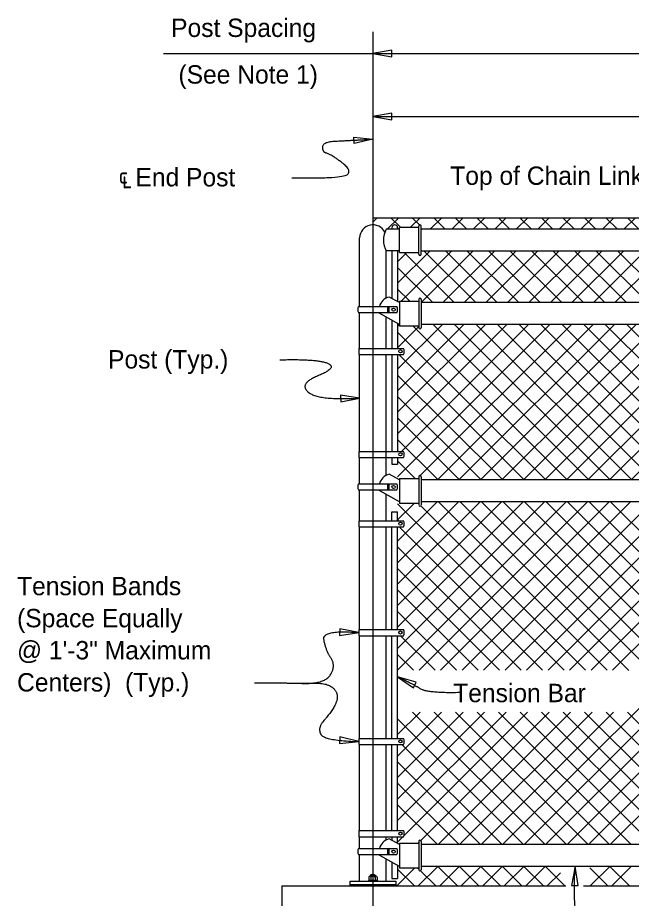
# Model space of a CAD drawing. Extents: x 110341.7 to 110413.5, y 110387.3 to 110417.8.
# Drawn here: x 110341.68 to 110348.41, y 110405.96 to 110415.62 of the extents above; entities that cross this region are included whole.
import ezdxf

# ---------------------------------------------------------------- set-up
doc = ezdxf.new("R2010")
doc.units = 0
for name, color, linetype in [('AdhocPoint_dp', 7, 'Continuous'), ('Border', 7, 'Continuous'), ('CL_Major', 7, 'Continuous'), ('Patterning', 7, 'Continuous'), ('PlotBorder_dp', 7, 'Continuous'), ('SheetBorder_dp', 7, 'Continuous')]:
    doc.layers.add(name, color=color, linetype=linetype)

msp = doc.modelspace()

# ---------------------------------------------------------------- linework, layer by layer
at = {"layer": 'AdhocPoint_dp'}
for p, q in [((110345.7862, 110413.3133), (110345.7862, 110413.2957)), ((110345.8487, 110413.3133), (110345.8487, 110413.2957)), ((110345.8673, 110413.0415), (110345.8673, 110413.3138)), ((110346.0803, 110413.3138), (110345.8673, 110413.3138)), ((110346.0803, 110413.022), (110346.0803, 110413.3316)), ((110346.1071, 110413.022), (110346.1071, 110413.3316)), ((110345.8674, 110413.2957), (110345.7237, 110413.2957)), ((110355.0484, 110413.2966), (110346.1071, 110413.2966)), ((110345.432, 110412.4493), (110345.432, 110413.2019)), ((110345.7237, 110412.5385), (110345.7237, 110413.058)), ((110345.8674, 110413.058), (110345.7237, 110413.058)), ((110345.7862, 110413.058), (110345.7862, 110412.5385)), ((110345.8487, 110413.058), (110345.8487, 110412.5023)), ((110345.8673, 110413.0415), (110346.0803, 110413.0415)), ((110355.0484, 110413.057), (110346.1071, 110413.057)), ((110345.8673, 110412.4919), (110345.7565, 110412.5532)), ((110345.4206, 110412.4493), (110345.8402, 110412.4493)), ((110345.7578, 110412.4415), (110345.7343, 110412.4415)), ((110345.8673, 110412.5066), (110345.8673, 110412.2344)), ((110345.8673, 110412.5066), (110346.0803, 110412.5066)), ((110346.0803, 110412.5261), (110346.0803, 110412.2165)), ((110346.1071, 110412.5261), (110346.1071, 110412.2165)), ((110355.0484, 110412.4912), (110346.1071, 110412.4912)), ((110345.4205, 110412.3815), (110345.8402, 110412.3815)), ((110345.432, 110411.9892), (110345.432, 110412.3815)), ((110345.8673, 110412.2525), (110345.6534, 110412.371)), ((110345.7578, 110412.4319), (110345.7343, 110412.4319)), ((110345.7578, 110412.421), (110345.7343, 110412.421)), ((110345.7578, 110412.4093), (110345.7343, 110412.4093)), ((110345.7578, 110412.3975), (110345.7343, 110412.3975)), ((110345.7578, 110412.3877), (110345.7343, 110412.3877)), ((110345.7237, 110411.9891), (110345.7237, 110412.3321)), ((110345.7862, 110412.2975), (110345.7862, 110411.9892)), ((110345.8487, 110412.2629), (110345.8487, 110411.9892)), ((110355.0484, 110412.2516), (110346.1071, 110412.2516)), ((110346.0803, 110412.2344), (110345.8673, 110412.2344)), ((110345.422, 110411.9891), (110345.9131, 110411.9891)), ((110345.422, 110411.9891), (110345.422, 110411.9215)), ((110345.422, 110411.9215), (110345.9123, 110411.9215)), ((110345.432, 110410.8603), (110345.432, 110411.9216)), ((110345.7237, 110410.5969), (110345.7237, 110411.9215)), ((110345.7862, 110411.9216), (110345.7862, 110410.8603)), ((110345.8487, 110411.9216), (110345.8487, 110410.8603)), ((110345.422, 110410.8603), (110345.9131, 110410.8603)), ((110345.422, 110410.8603), (110345.422, 110410.7927)), ((110345.422, 110410.7927), (110345.9123, 110410.7927)), ((110345.432, 110410.5048), (110345.432, 110410.7927)), ((110345.7862, 110410.7927), (110345.7862, 110410.718)), ((110345.8487, 110410.7927), (110345.8487, 110410.718)), ((110345.7862, 110410.718), (110345.8487, 110410.718)), ((110345.8673, 110410.5473), (110345.7565, 110410.6087)), ((110345.4206, 110410.5047), (110345.8402, 110410.5047)), ((110345.8673, 110410.5621), (110345.8673, 110410.2898)), ((110345.8673, 110410.5621), (110346.0803, 110410.5621)), ((110346.0803, 110410.5816), (110346.0803, 110410.272)), ((110346.1071, 110410.5816), (110346.1071, 110410.272)), ((110355.0484, 110410.5466), (110346.1071, 110410.5466)), ((110345.4205, 110410.4369), (110345.8402, 110410.4369)), ((110345.432, 110410.1), (110345.432, 110410.4369)), ((110345.8673, 110410.308), (110345.6534, 110410.4265)), ((110345.7578, 110410.4969), (110345.7343, 110410.4969)), ((110345.7578, 110410.4873), (110345.7343, 110410.4873)), ((110345.7578, 110410.4765), (110345.7343, 110410.4765)), ((110345.7578, 110410.4647), (110345.7343, 110410.4647)), ((110345.7578, 110410.453), (110345.7343, 110410.453)), ((110345.7578, 110410.4432), (110345.7343, 110410.4432)), ((110345.7237, 110410.1), (110345.7237, 110410.3876)), ((110346.0803, 110410.2898), (110345.8673, 110410.2898)), ((110355.0484, 110410.307), (110346.1071, 110410.307)), ((110345.7862, 110410.1982), (110345.8487, 110410.1982)), ((110345.7862, 110410.1), (110345.7862, 110410.1982)), ((110345.8487, 110410.1), (110345.8487, 110410.1982)), ((110345.422, 110410.1), (110345.422, 110410.0324)), ((110345.422, 110410.1), (110345.9131, 110410.1)), ((110345.422, 110410.0324), (110345.9123, 110410.0324)), ((110345.432, 110408.9056), (110345.432, 110410.0324)), ((110345.7237, 110408.9056), (110345.7237, 110410.0324)), ((110345.7862, 110408.9056), (110345.7862, 110410.0324)), ((110345.8487, 110408.9056), (110345.8487, 110410.0324)), ((110345.422, 110408.9056), (110345.422, 110408.838)), ((110345.422, 110408.9056), (110345.9131, 110408.9056)), ((110345.422, 110408.838), (110345.9123, 110408.838)), ((110345.432, 110407.7111), (110345.432, 110408.838)), ((110345.7237, 110407.7111), (110345.7237, 110408.838)), ((110345.7862, 110407.7111), (110345.7862, 110408.838)), ((110345.8487, 110407.7111), (110345.8487, 110408.838)), ((110345.422, 110407.7111), (110345.422, 110407.6435)), ((110345.422, 110407.7111), (110345.9131, 110407.7111)), ((110345.422, 110407.6435), (110345.9123, 110407.6435)), ((110345.432, 110406.7008), (110345.432, 110407.6435)), ((110345.7237, 110406.7008), (110345.7237, 110407.6435)), ((110345.7862, 110406.7008), (110345.7862, 110407.6435)), ((110345.8487, 110406.7008), (110345.8487, 110407.6435)), ((110345.422, 110406.7008), (110345.422, 110406.6332)), ((110345.422, 110406.7008), (110345.9131, 110406.7008)), ((110345.422, 110406.6332), (110345.9123, 110406.6332)), ((110345.432, 110406.5047), (110345.432, 110406.6332)), ((110345.7237, 110406.5968), (110345.7237, 110406.6332)), ((110345.8673, 110406.5473), (110345.7565, 110406.6087)), ((110345.7862, 110406.6332), (110345.7862, 110406.5922)), ((110345.8487, 110406.5576), (110345.8487, 110406.6332)), ((110345.8673, 110406.5621), (110345.8673, 110406.2898)), ((110345.8673, 110406.5621), (110346.0803, 110406.5621)), ((110346.0803, 110406.5816), (110346.0803, 110406.2719)), ((110346.1071, 110406.5816), (110346.1071, 110406.2719)), ((110355.0484, 110406.5466), (110346.1071, 110406.5466)), ((110345.4206, 110406.5047), (110345.8402, 110406.5047)), ((110345.7578, 110406.4969), (110345.7343, 110406.4969)), ((110345.7578, 110406.4873), (110345.7343, 110406.4873)), ((110345.7578, 110406.4765), (110345.7343, 110406.4765)), ((110345.7578, 110406.4647), (110345.7343, 110406.4647)), ((110345.7578, 110406.4529), (110345.7343, 110406.4529)), ((110345.4205, 110406.4369), (110345.8402, 110406.4369)), ((110345.432, 110406.1455), (110345.432, 110406.4369)), ((110345.8673, 110406.3079), (110345.6534, 110406.4265)), ((110345.7237, 110406.1455), (110345.7237, 110406.3875)), ((110345.7578, 110406.4431), (110345.7343, 110406.4431)), ((110345.7862, 110406.3529), (110345.7862, 110406.1768)), ((110345.8487, 110406.3183), (110345.8487, 110406.1768)), ((110346.0803, 110406.2898), (110345.8673, 110406.2898)), ((110355.0484, 110406.307), (110346.1071, 110406.307)), ((110345.5324, 110406.1903), (110345.5324, 110406.1526)), ((110345.6119, 110406.199), (110345.5437, 110406.199)), ((110345.5617, 110406.2199), (110345.552, 110406.2102)), ((110345.552, 110406.2102), (110345.552, 110406.199)), ((110345.552, 110406.2102), (110345.6035, 110406.2102)), ((110345.5551, 110406.1905), (110345.5551, 110406.1526)), ((110345.5617, 110406.2199), (110345.5922, 110406.2199)), ((110345.5922, 110406.2199), (110345.6035, 110406.2102)), ((110345.6005, 110406.1905), (110345.6005, 110406.1526)), ((110345.6035, 110406.2102), (110345.6035, 110406.199)), ((110345.6232, 110406.1903), (110345.6232, 110406.1526)), ((110345.7862, 110406.1768), (110345.8487, 110406.1768)), ((110345.458, 110406.1039), (110345.6976, 110406.1039)), ((110345.5281, 110406.1526), (110345.5281, 110406.1455)), ((110345.5281, 110406.1526), (110345.6276, 110406.1526)), ((110345.6232, 110406.1526), (110345.5324, 110406.1526)), ((110345.6276, 110406.1526), (110345.6276, 110406.1455))]:
    msp.add_line(p, q, dxfattribs=at)
msp.add_lwpolyline([(110345.3278, 110406.1455), (110345.8278, 110406.1455), (110345.8278, 110406.1039), (110345.3278, 110406.1039)], close=True, dxfattribs=at)
for centre, radius, start, end in [((110345.5778, 110413.1987), 0.1459, 26.2486, 178.74846), ((110345.8174, 110413.3133), 0.0312, 0, 180), ((110346.0936, 110413.332), 0.0134, 0, 180), ((110345.9373, 110413.1768), 0.2445, 150.92084, 209.07916), ((110346.0936, 110413.0222), 0.0134, 180, 0), ((110346.0936, 110412.5261), 0.0134, 0, 180), ((110346.0936, 110412.2163), 0.0134, 180, 0), ((110346.0936, 110410.5815), 0.0134, 0, 180), ((110346.0936, 110410.2717), 0.0134, 180, 0), ((110346.0936, 110406.5815), 0.0134, 0, 180), ((110346.0936, 110406.2717), 0.0134, 180, 0), ((110345.5438, 110406.1871), 0.0118, 16.59863, 164.70054), ((110345.5778, 110406.1642), 0.0347, 49.20147, 130.79853), ((110345.6118, 110406.1872), 0.0118, 15.15064, 163.50417)]:
    msp.add_arc(centre, radius, start, end, dxfattribs=at)
for centre, major_axis, start_param, end_param in [((110345.791, 110412.4173), (-0.146, 0), 4.95193, 6.05206), ((110345.4896, 110412.4153), (-0.0776, 0), 5.807767, 6.754779), ((110345.771, 110412.4153), (0.0776, 0), 5.810211, 6.75616), ((110345.791, 110412.4173), (-0.146, 0), 0.258558, 0.335209), ((110345.8436, 110411.956), (0.0776, 0), 5.801046, 6.744962), ((110345.8436, 110410.8272), (0.0776, 0), 5.801046, 6.744962), ((110345.791, 110410.4727), (-0.146, 0), 4.95193, 6.05206), ((110345.4896, 110410.4708), (-0.0776, 0), 5.807767, 6.754779), ((110345.771, 110410.4707), (0.0776, 0), 5.810211, 6.75616), ((110345.791, 110410.4727), (-0.146, 0), 0.258558, 0.335209), ((110345.8436, 110410.0669), (0.0776, 0), 5.800848, 6.744767), ((110345.8436, 110408.8725), (0.0776, 0), 5.801046, 6.744962), ((110345.8436, 110407.6781), (0.0776, 0), 5.810211, 6.745158), ((110345.8436, 110406.6677), (0.0776, 0), 5.800848, 6.744767), ((110345.791, 110406.4727), (-0.146, 0), 4.95193, 6.05206), ((110345.4896, 110406.4708), (-0.0776, 0), 5.807767, 6.754779), ((110345.771, 110406.4707), (0.0776, 0), 5.810211, 6.75616), ((110345.791, 110406.4727), (-0.146, 0), 0.258558, 0.335209)]:
    msp.add_ellipse(centre, major_axis=major_axis, ratio=0.957868, start_param=start_param, end_param=end_param, dxfattribs=at)
for centre, major_axis in [((110345.8044, 110412.4148), (-0.0178, 0)), ((110345.8795, 110411.9564), (-0.0177, 0)), ((110345.8795, 110410.8276), (-0.0177, 0)), ((110345.8044, 110410.4703), (-0.0178, 0)), ((110345.8795, 110410.0673), (-0.0177, 0)), ((110345.8795, 110408.8729), (-0.0177, 0)), ((110345.8795, 110407.6785), (-0.0177, 0)), ((110345.8795, 110406.6681), (-0.0177, 0)), ((110345.8044, 110406.4703), (-0.0178, 0))]:
    msp.add_ellipse(centre, major_axis=major_axis, ratio=0.957868, dxfattribs=at)
at = {"layer": 'Border'}
for p, q in [((110343.2819, 110415.2246), (110354.5778, 110415.2246)), ((110345.5778, 110414.5336), (110355.5778, 110414.5336)), ((110345.5778, 110406.1533), (110345.5778, 110406.1526))]:
    msp.add_line(p, q, dxfattribs=at)
for points in [[(110345.5778, 110415.2246), (110345.786, 110415.1893), (110345.786, 110415.2599)], [(110345.5778, 110414.5336), (110345.786, 110414.4983), (110345.786, 110414.5689)], [(110345.5778, 110414.2843), (110345.3717, 110414.2377), (110345.3679, 110414.3082)], [(110345.432, 110411.4438), (110345.2231, 110411.4753), (110345.2244, 110411.4048)], [(110345.422, 110408.8718), (110345.2147, 110408.9124), (110345.2129, 110408.8418)], [(110345.8486, 110408.3863), (110346.0223, 110408.266), (110346.0522, 110408.3299)], [(110345.422, 110407.6773), (110345.2167, 110407.7272), (110345.2118, 110407.6568)], [(110347.7928, 110406.307), (110347.7551, 110406.0992), (110347.8256, 110406.0983)]]:
    msp.add_lwpolyline(points, close=True, dxfattribs=at)
for points in [[(110344.6883, 110413.8606), (110345.234, 110413.8508), (110345.3565, 110413.9397), (110345.1123, 110414.121), (110345.0274, 110414.1393), (110345.0274, 110414.2572), (110345.3055, 110414.2694), (110345.5778, 110414.2843)], [(110344.5591, 110411.8642), (110344.9628, 110411.8757), (110345.1958, 110411.7787), (110344.761, 110411.6009), (110344.9767, 110411.4185), (110345.432, 110411.4438)], [(110344.2805, 110408.3227), (110344.5557, 110408.3227), (110345.0469, 110408.3079), (110345.1744, 110408.5069), (110345.0622, 110408.6754), (110345.0194, 110408.9096), (110345.422, 110408.8718)], [(110346.5469, 110408.2144), (110346.1792, 110408.2052), (110346.0222, 110408.3033), (110345.8487, 110408.3863)], [(110344.5507, 110408.3221), (110344.7919, 110408.313), (110345.0849, 110408.3216), (110345.2105, 110408.1958), (110345.1389, 110408.0174), (110344.9638, 110407.824), (110345.0503, 110407.687), (110345.422, 110407.6773)], [(110348.3978, 110405.4486), (110348.0551, 110405.4333), (110347.7577, 110405.6365), (110347.7928, 110406.307)]]:
    msp.add_open_spline(points, degree=2, dxfattribs=at)
at = {"layer": 'CL_Major'}
msp.add_line((110345.5778, 110415.4617), (110345.5778, 110401.2111), dxfattribs=at)
at = {"layer": 'Patterning'}
for p, q in [((110345.5778, 110413.4227), (110356.9648, 110413.4227)), ((110345.5778, 110413.3753), (110345.6251, 110413.4227)), ((110345.7338, 110413.2957), (110345.8608, 110413.4227)), ((110345.7736, 110413.4227), (110345.8825, 110413.3138)), ((110345.9876, 110413.3138), (110346.0965, 110413.4227)), ((110346.0093, 110413.4227), (110346.0874, 110413.3446)), ((110346.2062, 110413.2966), (110346.3322, 110413.4227)), ((110346.245, 110413.4227), (110346.371, 110413.2966)), ((110346.4419, 110413.2966), (110346.5679, 110413.4227)), ((110346.4807, 110413.4227), (110346.6067, 110413.2966)), ((110346.6776, 110413.2966), (110346.8036, 110413.4227)), ((110346.7164, 110413.4227), (110346.8425, 110413.2966)), ((110346.9133, 110413.2966), (110347.0394, 110413.4227)), ((110346.9521, 110413.4227), (110347.0782, 110413.2966)), ((110347.149, 110413.2966), (110347.2751, 110413.4227)), ((110347.1878, 110413.4227), (110347.3139, 110413.2966)), ((110347.3847, 110413.2966), (110347.5108, 110413.4227)), ((110347.4235, 110413.4227), (110347.5496, 110413.2966)), ((110347.6204, 110413.2966), (110347.7465, 110413.4227)), ((110347.6592, 110413.4227), (110347.7853, 110413.2966)), ((110347.8561, 110413.2966), (110347.9822, 110413.4227)), ((110347.8949, 110413.4227), (110348.021, 110413.2966)), ((110348.0918, 110413.2966), (110348.2179, 110413.4227)), ((110348.1306, 110413.4227), (110348.2567, 110413.2966)), ((110348.3275, 110413.2966), (110348.4536, 110413.4227)), ((110348.3663, 110413.4227), (110348.4924, 110413.2966)), ((110345.8487, 110412.7034), (110346.2023, 110413.057)), ((110345.8487, 110412.9391), (110345.9511, 110413.0415)), ((110345.8876, 110412.5066), (110346.438, 110413.057)), ((110345.919, 110413.0415), (110346.4694, 110412.4912)), ((110346.1078, 110412.4912), (110346.6737, 110413.057)), ((110346.1392, 110413.057), (110346.7051, 110412.4912)), ((110346.3435, 110412.4912), (110346.9094, 110413.057)), ((110346.3749, 110413.057), (110346.9408, 110412.4912)), ((110346.5792, 110412.4912), (110347.1451, 110413.057)), ((110346.6106, 110413.057), (110347.1765, 110412.4912)), ((110346.815, 110412.4912), (110347.3808, 110413.057)), ((110346.8463, 110413.057), (110347.4122, 110412.4912)), ((110347.0507, 110412.4912), (110347.6165, 110413.057)), ((110347.082, 110413.057), (110347.6479, 110412.4912)), ((110347.2864, 110412.4912), (110347.8522, 110413.057)), ((110347.3177, 110413.057), (110347.8836, 110412.4912)), ((110347.5221, 110412.4912), (110348.0879, 110413.057)), ((110347.5534, 110413.057), (110348.1193, 110412.4912)), ((110347.7578, 110412.4912), (110348.3236, 110413.057)), ((110347.7891, 110413.057), (110348.355, 110412.4912)), ((110347.9935, 110412.4912), (110348.5593, 110413.057)), ((110348.0248, 110413.057), (110348.5907, 110412.4912)), ((110348.2292, 110412.4912), (110348.795, 110413.057)), ((110348.2605, 110413.057), (110348.8264, 110412.4912)), ((110345.8487, 110412.8762), (110346.2337, 110412.4912)), ((110345.8487, 110412.6405), (110345.9778, 110412.5113)), ((110345.8487, 110411.7606), (110346.3397, 110412.2516)), ((110345.8487, 110411.2892), (110346.8111, 110412.2516)), ((110345.8487, 110410.5821), (110347.5182, 110412.2516)), ((110345.8487, 110411.0535), (110347.0468, 110412.2516)), ((110345.8487, 110411.5249), (110346.5754, 110412.2516)), ((110345.8487, 110412.232), (110345.8674, 110412.2507)), ((110345.8912, 110410.8603), (110347.2825, 110412.2516)), ((110346.0969, 110410.5946), (110347.7539, 110412.2516)), ((110346.2376, 110412.2516), (110347.9425, 110410.5466)), ((110346.2846, 110410.5466), (110347.9896, 110412.2516)), ((110346.4733, 110412.2516), (110348.1782, 110410.5466)), ((110346.5203, 110410.5466), (110348.2253, 110412.2516)), ((110346.709, 110412.2516), (110348.4139, 110410.5466)), ((110346.756, 110410.5466), (110348.461, 110412.2516)), ((110346.9447, 110412.2516), (110348.6496, 110410.5466)), ((110346.9917, 110410.5466), (110348.6967, 110412.2516)), ((110347.1804, 110412.2516), (110348.8853, 110410.5466)), ((110347.2274, 110410.5466), (110348.9324, 110412.2516)), ((110347.4161, 110412.2516), (110349.121, 110410.5466)), ((110347.4631, 110410.5466), (110349.1681, 110412.2516)), ((110347.6518, 110412.2516), (110349.3567, 110410.5466)), ((110347.6988, 110410.5466), (110349.4038, 110412.2516)), ((110347.8875, 110412.2516), (110349.5925, 110410.5466)), ((110347.9345, 110410.5466), (110349.6395, 110412.2516)), ((110348.1232, 110412.2516), (110349.8282, 110410.5466)), ((110348.1702, 110410.5466), (110349.8752, 110412.2516)), ((110348.3589, 110412.2516), (110350.0639, 110410.5466)), ((110348.4059, 110410.5466), (110350.1109, 110412.2516)), ((110345.8487, 110411.9963), (110346.0803, 110412.228)), ((110345.8487, 110412.1691), (110347.4711, 110410.5466)), ((110346.0191, 110412.2344), (110347.7068, 110410.5466)), ((110345.8605, 110411.9216), (110347.2354, 110410.5466)), ((110345.8487, 110411.6977), (110346.9997, 110410.5466)), ((110345.8487, 110411.462), (110346.764, 110410.5466)), ((110345.8487, 110411.2263), (110346.5283, 110410.5466)), ((110345.8487, 110410.9906), (110346.2926, 110410.5466)), ((110345.8487, 110410.7549), (110346.0414, 110410.5621)), ((110345.8487, 110408.9322), (110347.2235, 110410.307)), ((110345.8487, 110409.4036), (110346.7521, 110410.307)), ((110345.8487, 110408.6965), (110347.4593, 110410.307)), ((110345.8487, 110409.1679), (110346.9878, 110410.307)), ((110345.8487, 110409.6393), (110346.5164, 110410.307)), ((110345.8487, 110408.4608), (110347.695, 110410.307)), ((110345.8487, 110409.875), (110346.2807, 110410.307)), ((110345.8487, 110410.1107), (110346.0279, 110410.2899)), ((110345.8487, 110410.2835), (110347.6726, 110408.4596)), ((110346.0832, 110408.4596), (110347.9307, 110410.307)), ((110346.1043, 110410.2635), (110347.9083, 110408.4596)), ((110346.2965, 110410.307), (110348.144, 110408.4596)), ((110346.3189, 110408.4596), (110348.1664, 110410.307)), ((110346.5322, 110410.307), (110348.3834, 110408.4558)), ((110346.5546, 110408.4596), (110348.4021, 110410.307)), ((110346.7679, 110410.307), (110350.5283, 110406.5466)), ((110346.7903, 110408.4596), (110348.6378, 110410.307)), ((110346.9986, 110406.5466), (110350.7591, 110410.307)), ((110347.0036, 110410.307), (110350.764, 110406.5466)), ((110347.026, 110408.4596), (110348.8735, 110410.307)), ((110347.2343, 110406.5466), (110350.9948, 110410.307)), ((110347.2393, 110410.307), (110350.9997, 110406.5466)), ((110347.2617, 110408.4596), (110349.1092, 110410.307)), ((110347.47, 110406.5466), (110351.2305, 110410.307)), ((110347.475, 110410.307), (110351.2355, 110406.5466)), ((110347.4974, 110408.4596), (110349.3449, 110410.307)), ((110347.7057, 110406.5466), (110351.4662, 110410.307)), ((110347.7107, 110410.307), (110351.4712, 110406.5466)), ((110347.7331, 110408.4596), (110349.5806, 110410.307)), ((110347.9415, 110406.5466), (110351.7019, 110410.307)), ((110347.9464, 110410.307), (110351.7069, 110406.5466)), ((110347.9688, 110408.4596), (110349.8163, 110410.307)), ((110348.1772, 110406.5466), (110351.9376, 110410.307)), ((110348.1821, 110410.307), (110351.9426, 110406.5466)), ((110348.2045, 110408.4596), (110350.052, 110410.307)), ((110345.8487, 110410.1121), (110345.8607, 110410.1)), ((110345.864, 110410.0324), (110347.4369, 110408.4596)), ((110345.8504, 110409.8103), (110347.2012, 110408.4596)), ((110345.8487, 110409.5764), (110346.9655, 110408.4596)), ((110345.8487, 110409.3407), (110346.7298, 110408.4596)), ((110345.8487, 110409.105), (110346.4941, 110408.4596)), ((110345.8799, 110408.838), (110346.2584, 110408.4596)), ((110345.8487, 110408.6336), (110346.0227, 110408.4596)), ((110345.8487, 110407.0465), (110346.8013, 110407.9992)), ((110345.8487, 110406.8108), (110347.037, 110407.9992)), ((110345.8487, 110407.518), (110346.3299, 110407.9992)), ((110345.8487, 110407.2823), (110346.5656, 110407.9992)), ((110345.8487, 110407.7537), (110346.0942, 110407.9992)), ((110345.917, 110406.6435), (110347.2728, 110407.9992)), ((110346.0116, 110407.9992), (110347.4642, 110406.5466)), ((110346.1016, 110406.5923), (110347.5085, 110407.9992)), ((110346.2473, 110407.9992), (110347.6999, 110406.5466)), ((110346.2915, 110406.5466), (110347.7442, 110407.9992)), ((110346.483, 110407.9992), (110347.9356, 110406.5466)), ((110346.5272, 110406.5466), (110347.9799, 110407.9992)), ((110346.7187, 110407.9992), (110348.1713, 110406.5466)), ((110346.7629, 110406.5466), (110348.2156, 110407.9992)), ((110346.9544, 110407.9992), (110348.407, 110406.5466)), ((110347.1901, 110407.9992), (110348.6427, 110406.5466)), ((110347.4258, 110407.9992), (110348.8784, 110406.5466)), ((110347.6615, 110407.9992), (110349.1141, 110406.5466)), ((110347.8972, 110407.9992), (110349.3498, 110406.5466)), ((110348.1329, 110407.9992), (110349.5855, 110406.5466)), ((110348.3686, 110407.9992), (110349.8212, 110406.5466)), ((110345.8487, 110407.9265), (110347.2285, 110406.5466)), ((110345.8959, 110407.6435), (110346.9928, 110406.5466)), ((110345.8487, 110407.4551), (110346.7571, 110406.5466)), ((110345.8487, 110407.2193), (110346.5214, 110406.5466)), ((110345.8487, 110406.9836), (110346.2857, 110406.5466)), ((110345.8487, 110406.5751), (110345.9067, 110406.6332)), ((110346.0713, 110406.5621), (110346.0803, 110406.5711)), ((110345.8384, 110406.0935), (110346.0347, 110406.2898)), ((110345.8487, 110406.2765), (110346.0317, 110406.0935)), ((110346.0711, 110406.2898), (110346.0803, 110406.2806)), ((110346.0741, 110406.0935), (110346.2877, 110406.307)), ((110346.1007, 110406.2603), (110346.2674, 110406.0935)), ((110346.2896, 110406.307), (110346.5031, 110406.0935)), ((110346.3098, 110406.0935), (110346.5234, 110406.307)), ((110346.5253, 110406.307), (110346.7388, 110406.0935)), ((110346.5455, 110406.0935), (110346.7591, 110406.307)), ((110346.761, 110406.307), (110346.9745, 110406.0935)), ((110346.7812, 110406.0935), (110346.9948, 110406.307)), ((110346.9967, 110406.307), (110347.2103, 110406.0935)), ((110347.0169, 110406.0935), (110347.2305, 110406.307)), ((110347.2324, 110406.307), (110347.446, 110406.0935)), ((110347.2526, 110406.0935), (110347.4662, 110406.307)), ((110347.4681, 110406.307), (110347.6817, 110406.0935)), ((110347.9557, 110406.2908), (110348.1531, 110406.0935)), ((110347.9597, 110406.0935), (110348.1733, 110406.307)), ((110348.1752, 110406.307), (110348.3888, 110406.0935)), ((110348.1954, 110406.0935), (110348.409, 110406.307)), ((110345.5666, 110406.215), (110345.5874, 110406.215)), ((110345.5666, 110406.2053), (110345.5874, 110406.2053)), ((110347.4883, 110406.0935), (110347.6328, 110406.238)), ((110345.3278, 110406.1004), (110345.8278, 110406.1004)), ((110345.3278, 110406.0969), (110345.8278, 110406.0969))]:
    msp.add_line(p, q, dxfattribs=at)
msp.add_lwpolyline([(110345.3278, 110406.1039), (110345.8278, 110406.1039), (110345.8278, 110406.0935), (110345.3278, 110406.0935)], close=True, dxfattribs=at)
at = {"layer": 'PlotBorder_dp'}
for p, q in [((110344.5778, 110406.0935), (110344.5778, 110402.7185)), ((110344.5778, 110406.0935), (110347.6935, 110406.0935)), ((110347.8867, 110406.0935), (110356.9648, 110406.0935))]:
    msp.add_line(p, q, dxfattribs=at)

# ---------------------------------------------------------------- texts
at = {"layer": 'Border'}
for s, p in [('Tension Bands ', (110341.6781, 110409.2823)), ('(Space Equally ', (110341.6781, 110408.9303)), ('@ 1\'-3" Maximum ', (110341.6781, 110408.5783)), ('Centers)  (Typ.)', (110341.6781, 110408.2263))]:
    msp.add_text(s, height=0.2016, dxfattribs=at).set_placement(p)
at = {"layer": 'SheetBorder_dp'}
for s, p in [('Post Spacing', (110343.3663, 110415.4054)), ('(See Note 1)', (110343.4466, 110414.8939)), ('Top of Chain Link Fabric', (110346.425, 110413.7833)), ('℄ End Post', (110342.7912, 110413.7665)), ('Post (Typ.)', (110342.6753, 110411.7689)), ('Tension Bar', (110346.4576, 110408.1092))]:
    msp.add_text(s, height=0.2016, dxfattribs=at).set_placement(p)

doc.saveas('drawing.dxf')
